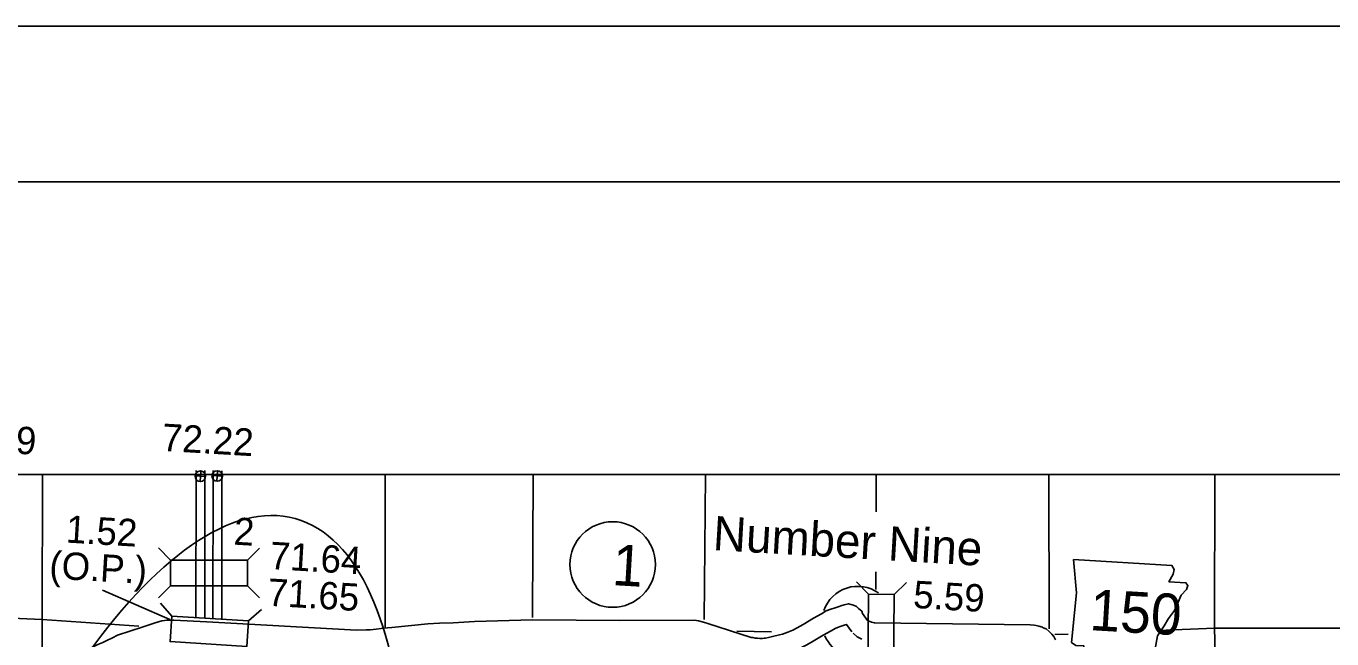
# Model space of a CAD drawing. Extents: x 1366406 to 1373462, y 376856 to 381998.
# Drawn here: x 1368242.9 to 1368569.5, y 381119.6 to 381272.9 of the extents above; entities that cross this region are included whole.
import ezdxf

# ---------------------------------------------------------------- set-up
doc = ezdxf.new("R2010")
doc.units = 0
for name, color, linetype in [('10', 7, 'Continuous'), ('19', 7, 'Continuous'), ('20', 7, 'Continuous'), ('21', 7, 'Continuous'), ('24', 7, 'Continuous'), ('25', 7, 'Continuous'), ('26', 7, 'Continuous'), ('27', 7, 'Continuous'), ('4', 7, 'Continuous'), ('5', 7, 'Continuous'), ('58', 7, 'Continuous'), ('Default', 7, 'Continuous'), ('R_Border', 7, 'Continuous'), ('R_No Plot', 7, 'Continuous')]:
    doc.layers.add(name, color=color, linetype=linetype)

msp = doc.modelspace()

# ---------------------------------------------------------------- linework, layer by layer
at = {"layer": '10'}
for points in [[(1368432.07, 381120.8), (1368433.37, 381121.31), (1368434.65, 381121.79), (1368435.74, 381122.38), (1368437.24, 381123.27), (1368439.82, 381124.81), (1368441.79, 381125.86), (1368443.01, 381126.62), (1368444.19, 381127.07), (1368445.22, 381127.4), (1368446.23, 381127.75), (1368446.66, 381127.88), (1368447.47, 381128.18), (1368448.55, 381128.43), (1368449.86, 381128.06), (1368450.58, 381127.69), (1368451.05, 381127.27), (1368451.9, 381126.53), (1368452.11, 381125.97), (1368453.35, 381124.27)], [(1368288.09, 381123.89), (1368279.89, 381124.32), (1368278.19, 381124.34), (1368276.88, 381124.11), (1368275.23, 381123.67), (1368271.92, 381122.56), (1368265.75, 381120.58), (1368264.51, 381119.89), (1368263.11, 381119.24), (1368262.1, 381118.76), (1368260.85, 381118.24), (1368259.56, 381117.58), (1368258.92, 381117.26), (1368258.49, 381117.1), (1368257.27, 381116.99), (1368255.13, 381116.43), (1368251.03, 381114.88), (1368246.39, 381113.22), (1368245.44, 381112.9), (1368244.25, 381112.38), (1368243.29, 381111.84), (1368242.98, 381111.68), (1368238.02, 381110.11)], [(1368288.1, 381123.89), (1368325.54, 381121.85), (1368327.96, 381121.9), (1368328.96, 381121.92), (1368330.46, 381122.08), (1368331.75, 381122.26), (1368333.28, 381122.38), (1368334.41, 381122.46), (1368343.41, 381123.41), (1368346.29, 381123.53), (1368349.73, 381123.67), (1368355.06, 381123.96), (1368369.58, 381124.38), (1368391.4, 381124.26), (1368410.03, 381124.3), (1368411.04, 381124.16), (1368412.3, 381123.85), (1368413.39, 381123.51), (1368424.24, 381120), (1368424.65, 381119.96), (1368425.22, 381119.85), (1368425.84, 381119.78), (1368426.43, 381119.75), (1368427.04, 381119.76), (1368427.47, 381119.78), (1368427.84, 381119.82), (1368428.55, 381119.94), (1368429.2, 381120.11), (1368429.88, 381120.31), (1368430.99, 381120.6), (1368432.44, 381120.91)], [(1368453.04, 381124.62), (1368453.52, 381124.16), (1368453.78, 381124.04), (1368454.35, 381123.85), (1368454.71, 381123.72), (1368455.07, 381123.63), (1368455.18, 381123.61), (1368494.03, 381123.18), (1368495.03, 381123.05), (1368495.49, 381122.97), (1368496.17, 381122.85), (1368497.09, 381122.53), (1368497.26, 381122.43), (1368498, 381122.17), (1368498.79, 381121.47), (1368499.2, 381121.05), (1368499.43, 381120.79), (1368499.95, 381120.24), (1368500.36, 381119.41)], [(1368433.85, 381116.28), (1368435.12, 381116.77), (1368436.66, 381117.36), (1368438.13, 381118.14), (1368439.72, 381119.09), (1368442.21, 381120.57), (1368444.23, 381121.65), (1368445.2, 381122.25), (1368445.8, 381122.49), (1368446.74, 381122.78), (1368447.74, 381123.13), (1368448.09, 381123.24), (1368449.41, 381121.42)], [(1368449.72, 381121.07), (1368450.74, 381120.11), (1368451.93, 381119.53)]]:
    msp.add_lwpolyline(points, dxfattribs=at)
at = {"layer": '19'}
for points in [[(1368285.39, 381124.87), (1368285.41, 381160.71)], [(1368285.41, 381161.43), (1368285.41, 381161.7)], [(1368285.41, 381161.43), (1368285.41, 381161.7)], [(1368287.62, 381124.73), (1368287.64, 381161.7)], [(1368289.64, 381124.6), (1368289.67, 381161.7)], [(1368291.87, 381124.47), (1368291.89, 381161.69)]]:
    msp.add_lwpolyline(points, dxfattribs=at)
at = {"layer": '20'}
for p, q in [((1368279.02, 381139.34), (1368275.99, 381142.36)), ((1368298.26, 381139.32), (1368301.29, 381142.35)), ((1368453.6, 381130.82), (1368450.61, 381133.87)), ((1368279.01, 381132.92), (1368275.99, 381129.9)), ((1368298.26, 381132.91), (1368301.28, 381129.88)), ((1368460.01, 381130.75), (1368463.07, 381133.74)), ((1368279.34, 381125.35), (1368276.51, 381128.56)), ((1368298.55, 381124.17), (1368301.75, 381127))]:
    msp.add_line(p, q, dxfattribs=at)
for points in [[(1368298.26, 381139.32), (1368279.02, 381139.34), (1368279.01, 381132.92), (1368298.26, 381132.91)], [(1368453.6, 381130.82), (1368453.38, 381111.57), (1368459.8, 381111.5), (1368460.01, 381130.75)], [(1368298.55, 381124.17), (1368279.34, 381125.35), (1368278.94, 381118.95), (1368298.15, 381117.76)]]:
    msp.add_lwpolyline(points, close=True, dxfattribs=at)
at = {"layer": '21'}
msp.add_lwpolyline([(1368504.87, 381139.45), (1368505.62, 381131.16), (1368504.34, 381118.75), (1368505.39, 381118), (1368507.44, 381117.88), (1368507.19, 381113.5), (1368524.42, 381112.49), (1368525.35, 381114.22), (1368525.24, 381117.11), (1368525.85, 381120.36), (1368527.5, 381122.87), (1368528.57, 381124.73), (1368530.06, 381126.71), (1368531.01, 381128.85), (1368531.8, 381130.58), (1368533.12, 381132.02), (1368533.45, 381132.96), (1368532.94, 381133.67), (1368528.7, 381133.92), (1368529.77, 381135.78), (1368529.98, 381137.01), (1368529.47, 381137.98)], close=True, dxfattribs=at)
at = {"layer": '24'}
for start, end in [(54.4007, 161.3743), (202.7248, 286.701)]:
    msp.add_arc((1368450.88, 381123.87), 8.91, start, end, dxfattribs=at)
at = {"layer": '26'}
for p, q in [((1368285.19, 381160.37), (1368287.81, 381160.22)), ((1368286.42, 381158.98), (1368286.58, 381161.61)), ((1368289.39, 381160.45), (1368292.02, 381160.3)), ((1368290.63, 381159.06), (1368290.79, 381161.69))]:
    msp.add_line(p, q, dxfattribs=at)
for centre in [(1368286.5, 381160.3), (1368290.71, 381160.37)]:
    msp.add_circle(centre, 1.32, dxfattribs=at)
at = {"layer": '27'}
msp.add_circle((1368389.6, 381138.23), 10.69, dxfattribs=at)
at = {"layer": '4'}
msp.add_lwpolyline([(1368332.68, 381160.56), (1368332.7, 381122.49)], dxfattribs=at)
at = {"layer": '5'}
for points in [[(1368247, 381160.73), (1368246.94, 381124.57), (1368246.92, 381114.02)], [(1368369.7, 381160.71), (1368369.57, 381125.01)], [(1368412.84, 381160.49), (1368412.52, 381124.49)], [(1368455.49, 381160.68), (1368455.47, 381151.39)], [(1368498.65, 381160.74), (1368498.72, 381122.17)], [(1368540.21, 381160.55), (1368540.06, 381122.38), (1368541.18, 381080.89)], [(1368455.44, 381136.36), (1368455.43, 381132.01)], [(1368227.81, 381125.31), (1368246.97, 381124.52), (1368271.14, 381122.8)], [(1368420.68, 381121.58), (1368429.33, 381121.4)], [(1368500.17, 381120.72), (1368503.51, 381120.85)], [(1368526.04, 381121.73), (1368540.07, 381122.28), (1368583.43, 381122.32)]]:
    msp.add_lwpolyline(points, dxfattribs=at)
at = {"layer": '58'}
msp.add_line((1368262.04, 381131.81), (1368278.9, 381124.45), dxfattribs=at)
at = {"layer": 'Default'}
msp.add_ellipse((1368265.23, 380986.62), major_axis=(44.98, 163.09), ratio=0.352669, dxfattribs=at)
at = {"layer": 'R_Border'}
msp.add_line((1367815.86, 381233.92), (1370977.66, 381233.92), dxfattribs=at)
at = {"layer": 'R_No Plot'}
msp.add_line((1367691.85, 381272.86), (1371025.18, 381272.86), dxfattribs=at)
msp.add_lwpolyline([(1367691.79, 381272.86), (1371025.18, 381272.86), (1371025.18, 379139.49), (1367691.79, 379139.49)], close=True, dxfattribs=at)
msp.add_lwpolyline([(1367869.99, 380474.3), (1367869.99, 381160.75), (1368650.02, 381160.75), (1368650.02, 380474.3), (1367869.99, 380474.3)], dxfattribs=at)

# ---------------------------------------------------------------- texts
at = {"layer": '20'}
msp.add_text('2', height=6.84, rotation=356.6294, dxfattribs=at).set_placement((1368294.71, 381143.21))
at = {"layer": '21'}
msp.add_text('150', height=10.264, rotation=356.6294, dxfattribs=at).set_placement((1368508.69, 381121.84))
at = {"layer": '24'}
msp.add_text('Number Nine', height=8.5536, rotation=356.6294, dxfattribs=at).set_placement((1368414.53, 381141.86))
at = {"layer": '25'}
for s, p in [('22.19', (1368222.42, 381167.01)), ('72.22', (1368276.75, 381166.66))]:
    msp.add_text(s, height=6.843, rotation=356.6294, dxfattribs=at).set_placement(p)
at = {"layer": '27'}
msp.add_text('1', height=10.26, rotation=356.6294, dxfattribs=at).set_placement((1368389.3, 381133.1))
at = {"layer": '58'}
for s, p in [('1.52', (1368252.74, 381143.73)), ('71.64', (1368303.7, 381137.11)), ('(O.P.)', (1368248.6, 381134.76)), ('71.65', (1368303.16, 381127.93)), ('5.59', (1368464.63, 381127.39))]:
    msp.add_text(s, height=6.843, rotation=356.6294, dxfattribs=at).set_placement(p)

doc.saveas('drawing.dxf')
